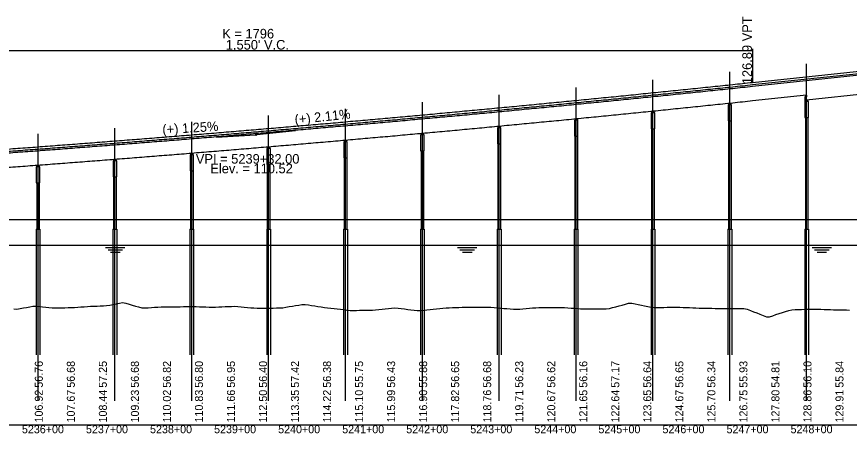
# Model space of a CAD drawing. Extents: x 2121671 to 2169879, y 557274 to 599957.
# Drawn here: x 2153126 to 2154426, y 579173 to 579824 of the extents above; entities that cross this region are included whole.
import ezdxf

# ---------------------------------------------------------------- set-up
doc = ezdxf.new("R2010")
doc.units = 0
for name, color, linetype in [('BR_CENTER LINES', 7, 'Continuous'), ('BR_CONCRETE', 7, 'Continuous'), ('BR_DETAILS', 7, 'Continuous'), ('BR_PRESTRESSED BEAM', 7, 'Continuous'), ('RD_DDB_GradeTX', 7, 'Continuous'), ('RD_DDB_Profile_Elev', 7, 'Continuous'), ('RD_DDB_Profile_EX', 7, 'Continuous'), ('RD_DDB_Profile_Lbl', 7, 'Continuous'), ('RD_DDB_Profile_PR', 7, 'Continuous'), ('RD_DDB_StaTX', 7, 'Continuous'), ('RD_DDB_StripGrade', 7, 'Continuous'), ('RD_DDB_VCLbl', 7, 'Continuous'), ('RD_GPK_Profile_Cell', 7, 'Continuous')]:
    doc.layers.add(name, color=color, linetype=linetype)

msp = doc.modelspace()

# ---------------------------------------------------------------- linework, layer by layer
at = {"layer": 'BR_CENTER LINES'}
for p, q in [((2154359.4, 579224.3), (2154359.4, 579750.2)), ((2154239.4, 579224.3), (2154239.4, 579737.6)), ((2154119.4, 579224.3), (2154119.4, 579725.2)), ((2153999.4, 579224.3), (2153999.4, 579713.3)), ((2153879.4, 579224.3), (2153879.4, 579701.7)), ((2153759.4, 579224.3), (2153759.4, 579690.5)), ((2153639.4, 579224.3), (2153639.4, 579679.8)), ((2153399.4, 579224.3), (2153399.4, 579659.5)), ((2153519.4, 579224.3), (2153519.4, 579669.4)), ((2153279.4, 579224.3), (2153279.4, 579649.9)), ((2153159.4, 579224.3), (2153159.4, 579640.8))]:
    msp.add_line(p, q, dxfattribs=at)
at = {"layer": 'BR_CONCRETE'}
for p, q in [((2154274.9, 579717.8), (2154567.9, 579748.7)), ((2154359.4, 579699), (2154356.7, 579699)), ((2154356.7, 579699), (2154356.7, 579666.7)), ((2154359.4, 579691.7), (2154359.4, 579699)), ((2154362.2, 579691.7), (2154359.4, 579691.7)), ((2154362.2, 579666.7), (2154362.2, 579691.7)), ((2154237.4, 579661.4), (2154237.4, 579492.4)), ((2154241.4, 579661.4), (2154241.4, 579492.4)), ((2154356.7, 579666.7), (2154362.2, 579666.7)), ((2154357.4, 579666.7), (2154357.4, 579492.4)), ((2154361.4, 579666.7), (2154361.4, 579492.4)), ((2154117.4, 579649), (2154117.4, 579492.4)), ((2154121.4, 579649), (2154121.4, 579492.4)), ((2153997.4, 579637.1), (2153997.4, 579492.4)), ((2154001.4, 579637.1), (2154001.4, 579492.4)), ((2153877.4, 579625.5), (2153877.4, 579492.4)), ((2153881.4, 579625.5), (2153881.4, 579492.4)), ((2153757.4, 579614.4), (2153757.4, 579492.4)), ((2153761.4, 579614.4), (2153761.4, 579492.4)), ((2153517.4, 579593.3), (2153517.4, 579492.4)), ((2153521.4, 579593.3), (2153521.4, 579492.4)), ((2153637.4, 579603.6), (2153637.4, 579492.4)), ((2153641.4, 579603.6), (2153641.4, 579492.4)), ((2153397.4, 579583.3), (2153397.4, 579492.4)), ((2153401.4, 579583.3), (2153401.4, 579492.4)), ((2153277.4, 579573.8), (2153277.4, 579492.4)), ((2153281.4, 579573.8), (2153281.4, 579492.4)), ((2153157.4, 579564.6), (2153157.4, 579492.4)), ((2153161.4, 579564.6), (2153161.4, 579492.4)), ((2153156.4, 579492.4), (2153156.4, 579296.1)), ((2153156.4, 579492.4), (2153162.4, 579492.4)), ((2153162.4, 579492.4), (2153162.4, 579296.1)), ((2153276.4, 579492.4), (2153276.4, 579296.1)), ((2153276.4, 579492.4), (2153282.4, 579492.4)), ((2153282.4, 579492.4), (2153282.4, 579296.1)), ((2153396.4, 579492.4), (2153396.4, 579296.1)), ((2153396.4, 579492.4), (2153402.4, 579492.4)), ((2153402.4, 579492.4), (2153402.4, 579296.1)), ((2153516.4, 579492.4), (2153516.4, 579296.1)), ((2153516.4, 579492.4), (2153522.4, 579492.4)), ((2153522.4, 579492.4), (2153522.4, 579296.1)), ((2153636.4, 579492.4), (2153636.4, 579296.1)), ((2153636.4, 579492.4), (2153642.4, 579492.4)), ((2153642.4, 579492.4), (2153642.4, 579296.1)), ((2153756.4, 579492.4), (2153756.4, 579296.1)), ((2153756.4, 579492.4), (2153762.4, 579492.4)), ((2153762.4, 579492.4), (2153762.4, 579296.1)), ((2153876.4, 579492.4), (2153876.4, 579296.1)), ((2153876.4, 579492.4), (2153882.4, 579492.4)), ((2153882.4, 579492.4), (2153882.4, 579296.1)), ((2153996.4, 579492.4), (2153996.4, 579296.1)), ((2153996.4, 579492.4), (2154002.4, 579492.4)), ((2154002.4, 579492.4), (2154002.4, 579296.1)), ((2154116.4, 579492.4), (2154116.4, 579296.1)), ((2154116.4, 579492.4), (2154122.4, 579492.4)), ((2154122.4, 579492.4), (2154122.4, 579296.1)), ((2154236.4, 579492.4), (2154236.4, 579296.1)), ((2154236.4, 579492.4), (2154242.4, 579492.4)), ((2154242.4, 579492.4), (2154242.4, 579296.1)), ((2154356.4, 579492.4), (2154356.4, 579296.1)), ((2154356.4, 579492.4), (2154362.4, 579492.4)), ((2154362.4, 579492.4), (2154362.4, 579296.1))]:
    msp.add_line(p, q, dxfattribs=at)
for points in [[(2154236.7, 579661.4), (2154242.2, 579661.4), (2154242.2, 579686.4), (2154236.7, 579686.4)], [(2154116.7, 579649), (2154122.2, 579649), (2154122.2, 579674), (2154116.7, 579674)], [(2153996.7, 579637.1), (2154002.2, 579637.1), (2154002.2, 579662.1), (2153996.7, 579662.1)], [(2153876.7, 579625.5), (2153882.2, 579625.5), (2153882.2, 579650.5), (2153876.7, 579650.5)], [(2153756.7, 579614.4), (2153762.2, 579614.4), (2153762.2, 579639.4), (2153756.7, 579639.4)], [(2153516.7, 579593.3), (2153522.2, 579593.3), (2153522.2, 579618.3), (2153516.7, 579618.3)], [(2153636.7, 579603.6), (2153642.2, 579603.6), (2153642.2, 579628.6), (2153636.7, 579628.6)], [(2153396.7, 579583.3), (2153402.2, 579583.3), (2153402.2, 579608.3), (2153396.7, 579608.3)], [(2153276.7, 579573.8), (2153282.2, 579573.8), (2153282.2, 579598.8), (2153276.7, 579598.8)], [(2153156.7, 579564.6), (2153162.2, 579564.6), (2153162.2, 579589.6), (2153156.7, 579589.6)]]:
    msp.add_lwpolyline(points, close=True, dxfattribs=at)
msp.add_spline([(2152724.9, 579587.5), (2152755.9, 579589.4), (2152786.9, 579591.4), (2152817.9, 579593.4), (2152848.9, 579595.4), (2152879.9, 579597.5), (2152910.9, 579599.6), (2152941.9, 579601.7), (2152972.9, 579603.8), (2153003.9, 579606), (2153034.9, 579608.2), (2153065.9, 579610.4), (2153096.9, 579612.6), (2153127.9, 579614.9), (2153158.9, 579617.2), (2153189.9, 579619.5), (2153220.9, 579621.9), (2153251.9, 579624.3), (2153282.9, 579626.7), (2153313.9, 579629.1), (2153344.9, 579631.6), (2153375.9, 579634), (2153406.9, 579636.6), (2153437.9, 579639.1), (2153468.9, 579641.7), (2153499.9, 579644.3), (2153530.9, 579646.9), (2153561.9, 579649.5), (2153592.9, 579652.2), (2153623.9, 579654.9), (2153654.9, 579657.6), (2153685.9, 579660.4), (2153716.9, 579663.1), (2153747.9, 579666), (2153778.9, 579668.8), (2153809.9, 579671.6), (2153840.9, 579674.5), (2153871.9, 579677.4), (2153902.9, 579680.4), (2153933.9, 579683.4), (2153964.9, 579686.3), (2153995.9, 579689.4), (2154026.9, 579692.4), (2154057.9, 579695.5), (2154088.9, 579698.6), (2154119.9, 579701.7), (2154150.9, 579704.9), (2154181.9, 579708.1), (2154212.9, 579711.3), (2154243.9, 579714.5), (2154274.9, 579717.8)], degree=3, dxfattribs=at)
at = {"layer": 'BR_DETAILS'}
for points in [[(2154357.9, 579701.5), (2154358.9, 579701.5), (2154358.9, 579699), (2154357.9, 579699)], [(2154237.9, 579688.9), (2154238.9, 579688.9), (2154238.9, 579686.4), (2154237.9, 579686.4)], [(2154239.9, 579688.9), (2154240.9, 579688.9), (2154240.9, 579686.4), (2154239.9, 579686.4)], [(2154359.9, 579694.2), (2154360.9, 579694.2), (2154360.9, 579691.7), (2154359.9, 579691.7)], [(2154117.9, 579676.5), (2154118.9, 579676.5), (2154118.9, 579674), (2154117.9, 579674)], [(2154119.9, 579676.5), (2154120.9, 579676.5), (2154120.9, 579674), (2154119.9, 579674)], [(2153997.9, 579664.6), (2153998.9, 579664.6), (2153998.9, 579662.1), (2153997.9, 579662.1)], [(2153999.9, 579664.6), (2154000.9, 579664.6), (2154000.9, 579662.1), (2153999.9, 579662.1)], [(2153877.9, 579653), (2153878.9, 579653), (2153878.9, 579650.5), (2153877.9, 579650.5)], [(2153879.9, 579653), (2153880.9, 579653), (2153880.9, 579650.5), (2153879.9, 579650.5)], [(2153637.9, 579631.1), (2153638.9, 579631.1), (2153638.9, 579628.6), (2153637.9, 579628.6)], [(2153639.9, 579631.1), (2153640.9, 579631.1), (2153640.9, 579628.6), (2153639.9, 579628.6)], [(2153757.9, 579641.9), (2153758.9, 579641.9), (2153758.9, 579639.4), (2153757.9, 579639.4)], [(2153759.9, 579641.9), (2153760.9, 579641.9), (2153760.9, 579639.4), (2153759.9, 579639.4)], [(2153517.9, 579620.8), (2153518.9, 579620.8), (2153518.9, 579618.3), (2153517.9, 579618.3)], [(2153519.9, 579620.8), (2153520.9, 579620.8), (2153520.9, 579618.3), (2153519.9, 579618.3)], [(2153397.9, 579610.8), (2153398.9, 579610.8), (2153398.9, 579608.3), (2153397.9, 579608.3)], [(2153399.9, 579610.8), (2153400.9, 579610.8), (2153400.9, 579608.3), (2153399.9, 579608.3)], [(2153157.9, 579592.1), (2153158.9, 579592.1), (2153158.9, 579589.6), (2153157.9, 579589.6)], [(2153159.9, 579592.1), (2153160.9, 579592.1), (2153160.9, 579589.6), (2153159.9, 579589.6)], [(2153277.9, 579601.3), (2153278.9, 579601.3), (2153278.9, 579598.8), (2153277.9, 579598.8)], [(2153279.9, 579601.3), (2153280.9, 579601.3), (2153280.9, 579598.8), (2153279.9, 579598.8)]]:
    msp.add_lwpolyline(points, close=True, dxfattribs=at)
at = {"layer": 'BR_PRESTRESSED BEAM'}
for p, q in [((2154274.9, 579715.3), (2154567.9, 579746.2)), ((2154359.4, 579694.2), (2154567.9, 579716.2)), ((2154274.9, 579692.8), (2154359.4, 579701.7))]:
    msp.add_line(p, q, dxfattribs=at)
for points in [[(2152724.9, 579585), (2152755.9, 579586.9), (2152786.9, 579588.9), (2152817.9, 579590.9), (2152848.9, 579592.9), (2152879.9, 579595), (2152910.9, 579597.1), (2152941.9, 579599.2), (2152972.9, 579601.3), (2153003.9, 579603.5), (2153034.9, 579605.7), (2153065.9, 579607.9), (2153096.9, 579610.1), (2153127.9, 579612.4), (2153158.9, 579614.7), (2153189.9, 579617), (2153220.9, 579619.4), (2153251.9, 579621.8), (2153282.9, 579624.2), (2153313.9, 579626.6), (2153344.9, 579629.1), (2153375.9, 579631.5), (2153406.9, 579634.1), (2153437.9, 579636.6), (2153468.9, 579639.2), (2153499.9, 579641.8), (2153530.9, 579644.4), (2153561.9, 579647), (2153592.9, 579649.7), (2153623.9, 579652.4), (2153654.9, 579655.1), (2153685.9, 579657.9), (2153716.9, 579660.6), (2153747.9, 579663.5), (2153778.9, 579666.3), (2153809.9, 579669.1), (2153840.9, 579672), (2153871.9, 579674.9), (2153902.9, 579677.9), (2153933.9, 579680.9), (2153964.9, 579683.8), (2153995.9, 579686.9), (2154026.9, 579689.9), (2154057.9, 579693), (2154088.9, 579696.1), (2154119.9, 579699.2), (2154150.9, 579702.4), (2154181.9, 579705.6), (2154212.9, 579708.8), (2154243.9, 579712), (2154274.9, 579715.3)], [(2152724.9, 579562.5), (2152755.9, 579564.4), (2152786.9, 579566.4), (2152817.9, 579568.4), (2152848.9, 579570.4), (2152879.9, 579572.5), (2152910.9, 579574.6), (2152941.9, 579576.7), (2152972.9, 579578.8), (2153003.9, 579581), (2153034.9, 579583.2), (2153065.9, 579585.4), (2153096.9, 579587.6), (2153127.9, 579589.9), (2153158.9, 579592.2), (2153189.9, 579594.5), (2153220.9, 579596.9), (2153251.9, 579599.3), (2153282.9, 579601.7), (2153313.9, 579604.1), (2153344.9, 579606.6), (2153375.9, 579609), (2153406.9, 579611.6), (2153437.9, 579614.1), (2153468.9, 579616.7), (2153499.9, 579619.3), (2153530.9, 579621.9), (2153561.9, 579624.5), (2153592.9, 579627.2), (2153623.9, 579629.9), (2153654.9, 579632.6), (2153685.9, 579635.4), (2153716.9, 579638.1), (2153747.9, 579641), (2153778.9, 579643.8), (2153809.9, 579646.6), (2153840.9, 579649.5), (2153871.9, 579652.4), (2153902.9, 579655.4), (2153933.9, 579658.4), (2153964.9, 579661.3), (2153995.9, 579664.4), (2154026.9, 579667.4), (2154057.9, 579670.5), (2154088.9, 579673.6), (2154119.9, 579676.7), (2154150.9, 579679.9), (2154181.9, 579683.1), (2154212.9, 579686.3), (2154243.9, 579689.5), (2154274.9, 579692.8)]]:
    msp.add_spline(points, degree=3, dxfattribs=at)
at = {"layer": 'RD_DDB_GradeTX'}
for p, q in [((2153561.6, 579645.9), (2153500.9, 579639.5)), ((2153438.1, 579635.6), (2153498.9, 579639.4))]:
    msp.add_line(p, q, dxfattribs=at)
msp.add_circle((2153499.9, 579639.4), 1, dxfattribs=at)
at = {"layer": 'RD_DDB_Profile_Elev'}
for p, q in [((2151922.4, 579507.4), (2155499.4, 579507.4)), ((2151953.5, 579467.4), (2156316.6, 579467.4)), ((2153265, 579463.7), (2153295, 579463.7)), ((2153814.5, 579463.7), (2153844.5, 579463.7)), ((2154368.1, 579463.7), (2154398.1, 579463.7)), ((2153268.8, 579459.9), (2153291.3, 579459.9)), ((2153272.5, 579456.2), (2153287.5, 579456.2)), ((2153818.2, 579459.9), (2153840.7, 579459.9)), ((2153822, 579456.2), (2153837, 579456.2)), ((2154371.8, 579459.9), (2154394.3, 579459.9)), ((2154375.6, 579456.2), (2154390.6, 579456.2))]:
    msp.add_line(p, q, dxfattribs=at)
at = {"layer": 'RD_DDB_Profile_EX'}
for points in [[(2153121.5, 579367.5), (2153126.5, 579367.4), (2153131.5, 579368.3), (2153136.5, 579369.2), (2153141.5, 579370.1), (2153146.5, 579371), (2153151.5, 579371.9), (2153156.5, 579371.9), (2153161.5, 579371.3), (2153166.5, 579370.8), (2153171.5, 579370.3), (2153176.5, 579369.7), (2153181.5, 579369.1), (2153186.5, 579369.2), (2153191.5, 579369.3), (2153196.5, 579369.4), (2153201.5, 579369.5), (2153206.5, 579369.6), (2153211.5, 579369.8), (2153216.5, 579370.1), (2153221.5, 579370.5)], [(2153221.5, 579370.5), (2153226.5, 579370.8), (2153231.5, 579371.1), (2153236.5, 579371.5), (2153241.5, 579371.7), (2153246.5, 579371.9), (2153251.5, 579372.1), (2153256.5, 579372.2), (2153261.5, 579372.4), (2153266.5, 579372.8), (2153271.5, 579373.7), (2153276.5, 579374.7), (2153281.5, 579375.6), (2153286.5, 579376.5), (2153291.5, 579377.5), (2153296.5, 579376.6), (2153301.5, 579375.1), (2153306.5, 579373.6), (2153311.5, 579372.1), (2153316.5, 579370.7), (2153321.5, 579369.2), (2153326.5, 579369.2), (2153331.5, 579369.5), (2153336.5, 579369.9), (2153341.5, 579370.2), (2153346.5, 579370.5), (2153351.5, 579370.8), (2153356.5, 579371.1), (2153361.5, 579370.9), (2153366.5, 579370.9), (2153371.5, 579371), (2153376.5, 579371), (2153381.5, 579371.1), (2153386.5, 579371.2), (2153391.5, 579371.2), (2153396.5, 579371.5), (2153401.5, 579371.3), (2153406.5, 579371.2), (2153411.5, 579371), (2153416.5, 579370.9), (2153421.5, 579370.7), (2153426.5, 579370.6), (2153431.5, 579370.4), (2153436.5, 579370.6), (2153441.5, 579370.8), (2153446.5, 579371), (2153451.5, 579371.2), (2153456.5, 579371.4), (2153461.5, 579371.6), (2153466.5, 579371.7), (2153471.5, 579371.3), (2153476.5, 579370.9), (2153481.5, 579370.4), (2153486.5, 579370), (2153491.5, 579369.5), (2153496.5, 579369.1), (2153501.5, 579368.6), (2153506.5, 579368.6), (2153511.5, 579368.7), (2153516.5, 579368.8), (2153521.5, 579368.9), (2153526.5, 579369), (2153531.5, 579369.1), (2153536.5, 579369.1), (2153541.5, 579369.5), (2153546.5, 579370.4), (2153551.5, 579371.2), (2153556.5, 579372), (2153561.5, 579372.9), (2153566.5, 579373.7), (2153571.5, 579374.5), (2153576.5, 579374.7), (2153581.5, 579374), (2153586.5, 579373.2), (2153591.5, 579372.4), (2153596.5, 579371.6), (2153601.5, 579370.9), (2153606.5, 579370.1), (2153611.5, 579369.5), (2153616.5, 579368.9), (2153621.5, 579368.3), (2153626.5, 579367.7), (2153631.5, 579367.1), (2153636.5, 579366.5), (2153641.5, 579365.9), (2153646.5, 579365.3), (2153651.5, 579365.4), (2153656.5, 579365.4), (2153661.5, 579365.5), (2153666.5, 579365.6), (2153671.5, 579365.6), (2153676.5, 579365.7), (2153681.5, 579365.8), (2153686.5, 579366.1), (2153691.5, 579366.6), (2153696.5, 579367.1), (2153701.5, 579367.6), (2153706.5, 579368.1), (2153711.5, 579368.6), (2153716.5, 579369.1), (2153721.5, 579368.8)], [(2153721.5, 579368.8), (2153726.5, 579368.1), (2153731.5, 579367.5), (2153736.5, 579366.9), (2153741.5, 579366.2), (2153746.5, 579365.6), (2153751.5, 579365), (2153756.5, 579365), (2153761.5, 579365.6), (2153766.5, 579366.1), (2153771.5, 579366.6), (2153776.5, 579367.2), (2153781.5, 579367.7), (2153786.5, 579368.2), (2153791.5, 579368.8), (2153796.5, 579369.3), (2153801.5, 579369.5), (2153806.5, 579369.7), (2153811.5, 579369.8), (2153816.5, 579370), (2153821.5, 579370.2), (2153826.5, 579370.4), (2153831.5, 579370.6), (2153836.5, 579370.6), (2153841.5, 579370.6), (2153846.5, 579370.5), (2153851.5, 579370.5), (2153856.5, 579370.4), (2153861.5, 579370.4), (2153866.5, 579370.3), (2153871.5, 579370), (2153876.5, 579369.5), (2153881.5, 579369), (2153886.5, 579368.5), (2153891.5, 579368.1), (2153896.5, 579367.6), (2153901.5, 579367.1), (2153906.5, 579367), (2153911.5, 579367.4), (2153916.5, 579367.8), (2153921.5, 579368.3), (2153926.5, 579368.7), (2153931.5, 579369.1), (2153936.5, 579369.5), (2153941.5, 579369.9), (2153946.5, 579369.9), (2153951.5, 579369.9), (2153956.5, 579369.9), (2153961.5, 579369.9), (2153966.5, 579369.9), (2153971.5, 579369.9), (2153976.5, 579369.9), (2153981.5, 579369.6), (2153986.5, 579369.2), (2153991.5, 579368.9), (2153996.5, 579368.6), (2154001.5, 579368.3), (2154006.5, 579367.9), (2154011.5, 579367.6), (2154016.5, 579367.6), (2154021.5, 579367.6), (2154026.5, 579367.6), (2154031.5, 579367.6), (2154036.5, 579367.6), (2154041.5, 579367.6), (2154046.5, 579367.5), (2154051.5, 579368.2), (2154056.5, 579369.6), (2154061.5, 579370.9), (2154066.5, 579372.3), (2154071.5, 579373.7), (2154076.5, 579375.1), (2154081.5, 579376.4), (2154086.5, 579376.6), (2154091.5, 579375.5), (2154096.5, 579374.5), (2154101.5, 579373.4), (2154106.5, 579372.3), (2154111.5, 579371.3), (2154116.5, 579370.2), (2154121.5, 579369.6), (2154126.5, 579369.7), (2154131.5, 579369.9), (2154136.5, 579370), (2154141.5, 579370.2), (2154146.5, 579370.3), (2154151.5, 579370.5), (2154156.5, 579370.6), (2154161.5, 579370.4), (2154166.5, 579370.1), (2154171.5, 579369.9), (2154176.5, 579369.6), (2154181.5, 579369.4), (2154186.5, 579369.1), (2154191.5, 579368.9), (2154196.5, 579368.8), (2154201.5, 579368.7), (2154206.5, 579368.7), (2154211.5, 579368.6), (2154216.5, 579368.5), (2154221.5, 579368.5)], [(2154221.5, 579368.5), (2154226.5, 579368.4), (2154231.5, 579368.4), (2154236.5, 579368.4), (2154241.5, 579368.3), (2154246.5, 579368.3), (2154251.5, 579368.2), (2154256.5, 579368.2), (2154261.5, 579368.2), (2154266.5, 579367), (2154271.5, 579365.1), (2154276.5, 579363.2), (2154281.5, 579361.3), (2154286.5, 579359.3), (2154291.5, 579357.4), (2154296.5, 579355.5), (2154301.5, 579355.3), (2154306.5, 579357), (2154311.5, 579358.7), (2154316.5, 579360.4), (2154321.5, 579362.1), (2154326.5, 579363.7), (2154331.5, 579365.4), (2154336.5, 579366.4), (2154341.5, 579366.6), (2154346.5, 579366.7), (2154351.5, 579366.9), (2154356.5, 579367), (2154361.5, 579367.2), (2154366.5, 579367.3), (2154371.5, 579367.3), (2154376.5, 579367.2), (2154381.5, 579367), (2154386.5, 579366.8), (2154391.5, 579366.7), (2154396.5, 579366.5), (2154401.5, 579366.3), (2154406.5, 579366.2), (2154411.5, 579366.1), (2154416.5, 579366), (2154421.5, 579366), (2154426.5, 579365.9)]]:
    msp.add_lwpolyline(points, dxfattribs=at)
at = {"layer": 'RD_DDB_Profile_PR'}
msp.add_line((2154274.9, 579721.3), (2154567.9, 579752.2), dxfattribs=at)
msp.add_spline([(2152724.9, 579591), (2152755.9, 579593), (2152786.9, 579594.9), (2152817.9, 579596.9), (2152848.9, 579599), (2152879.9, 579601), (2152910.9, 579603.1), (2152941.9, 579605.2), (2152972.9, 579607.4), (2153003.9, 579609.5), (2153034.9, 579611.7), (2153065.9, 579613.9), (2153096.9, 579616.2), (2153127.9, 579618.4), (2153158.9, 579620.7), (2153189.9, 579623.1), (2153220.9, 579625.4), (2153251.9, 579627.8), (2153282.9, 579630.2), (2153313.9, 579632.6), (2153344.9, 579635.1), (2153375.9, 579637.6), (2153406.9, 579640.1), (2153437.9, 579642.6), (2153468.9, 579645.2), (2153499.9, 579647.8), (2153530.9, 579650.4), (2153561.9, 579653.1), (2153592.9, 579655.7), (2153623.9, 579658.4), (2153654.9, 579661.2), (2153685.9, 579663.9), (2153716.9, 579666.7), (2153747.9, 579669.5), (2153778.9, 579672.3), (2153809.9, 579675.2), (2153840.9, 579678.1), (2153871.9, 579681), (2153902.9, 579683.9), (2153933.9, 579686.9), (2153964.9, 579689.9), (2153995.9, 579692.9), (2154026.9, 579696), (2154057.9, 579699), (2154088.9, 579702.1), (2154119.9, 579705.3), (2154150.9, 579708.4), (2154181.9, 579711.6), (2154212.9, 579714.8), (2154243.9, 579718), (2154274.9, 579721.3)], degree=3, dxfattribs=at)
at = {"layer": 'RD_DDB_VCLbl'}
for p, q in [((2152724.9, 579771.3), (2154274.9, 579771.3)), ((2154274.9, 579773.8), (2154274.9, 579721.3))]:
    msp.add_line(p, q, dxfattribs=at)
at = {"layer": 'RD_GPK_Profile_Cell'}
msp.add_line((2151067.9, 579186.8), (2157367.9, 579186.8), dxfattribs=at)

# ---------------------------------------------------------------- texts
at = {"layer": 'RD_DDB_GradeTX'}
for s, rotation, p in [('(+) 2.11%', 6.0299, (2153560.8, 579655.8)), ('(+) 1.25%', 3.5756, (2153354, 579640.2))]:
    msp.add_text(s, height=15, rotation=rotation, dxfattribs=at).set_placement(p)
at = {"layer": 'RD_DDB_Profile_Lbl'}
for s, p in [('VPI = 5239+32.00', (2153405.8, 579594.4)), ('Elev. = 110.52', (2153428.4, 579579.4))]:
    msp.add_text(s, height=15, dxfattribs=at).set_placement(p)
at = {"layer": 'RD_DDB_StaTX'}
for s, p in [('5236+00', (2153134.3, 579173.5)), ('5237+00', (2153234.3, 579173.5)), ('5238+00', (2153334.3, 579173.5)), ('5239+00', (2153434.3, 579173.5)), ('5240+00', (2153534.3, 579173.5)), ('5241+00', (2153634.3, 579173.5)), ('5242+00', (2153734.3, 579173.5)), ('5243+00', (2153834.3, 579173.5)), ('5244+00', (2153934.3, 579173.5)), ('5245+00', (2154034.3, 579173.5)), ('5246+00', (2154134.3, 579173.5)), ('5247+00', (2154234.3, 579173.5)), ('5248+00', (2154334.3, 579173.5))]:
    msp.add_text(s, height=12.5, dxfattribs=at).set_placement(p)
at = {"layer": 'RD_DDB_StripGrade'}
for s, height, p in [('126.89 VPT', 15, (2154273.9, 579718.5)), ('56.76', 12.5, (2153166.9, 579244.6)), ('56.68', 12.5, (2153216.9, 579244.6)), ('57.25', 12.5, (2153266.9, 579244.6)), ('56.68', 12.5, (2153316.9, 579244.6)), ('56.82', 12.5, (2153366.9, 579244.6)), ('56.80', 12.5, (2153416.9, 579244.6)), ('56.95', 12.5, (2153466.9, 579244.6)), ('56.40', 12.5, (2153516.9, 579244.6)), ('57.42', 12.5, (2153566.9, 579244.6)), ('56.38', 12.5, (2153616.9, 579244.6)), ('55.75', 12.5, (2153666.9, 579244.6)), ('56.43', 12.5, (2153716.9, 579244.6)), ('55.88', 12.5, (2153766.9, 579244.6)), ('56.65', 12.5, (2153816.9, 579244.6)), ('56.68', 12.5, (2153866.9, 579244.6)), ('56.23', 12.5, (2153916.9, 579244.6)), ('56.62', 12.5, (2153966.9, 579244.6)), ('56.16', 12.5, (2154016.9, 579244.6)), ('57.17', 12.5, (2154066.9, 579244.6)), ('56.64', 12.5, (2154116.9, 579244.6)), ('56.65', 12.5, (2154166.9, 579244.6)), ('56.34', 12.5, (2154216.9, 579244.6)), ('55.93', 12.5, (2154266.9, 579244.6)), ('54.81', 12.5, (2154316.9, 579244.6)), ('56.10', 12.5, (2154366.9, 579244.6)), ('55.84', 12.5, (2154416.9, 579244.6)), ('106.92', 12.5, (2153166.9, 579190.3)), ('107.67', 12.5, (2153216.9, 579190.3)), ('108.44', 12.5, (2153266.9, 579190.3)), ('109.23', 12.5, (2153316.9, 579190.3)), ('110.02', 12.5, (2153366.9, 579190.3)), ('110.83', 12.5, (2153416.9, 579190.3)), ('111.66', 12.5, (2153466.9, 579190.3)), ('112.50', 12.5, (2153516.9, 579190.3)), ('113.35', 12.5, (2153566.9, 579190.3)), ('114.22', 12.5, (2153616.9, 579190.3)), ('115.10', 12.5, (2153666.9, 579190.3)), ('115.99', 12.5, (2153716.9, 579190.3)), ('116.90', 12.5, (2153766.9, 579190.3)), ('117.82', 12.5, (2153816.9, 579190.3)), ('118.76', 12.5, (2153866.9, 579190.3)), ('119.71', 12.5, (2153916.9, 579190.3)), ('120.67', 12.5, (2153966.9, 579190.3)), ('121.65', 12.5, (2154016.9, 579190.3)), ('122.64', 12.5, (2154066.9, 579190.3)), ('123.65', 12.5, (2154116.9, 579190.3)), ('124.67', 12.5, (2154166.9, 579190.3)), ('125.70', 12.5, (2154216.9, 579190.3)), ('126.75', 12.5, (2154266.9, 579190.3)), ('127.80', 12.5, (2154316.9, 579190.3)), ('128.86', 12.5, (2154366.9, 579190.3)), ('129.91', 12.5, (2154416.9, 579190.3))]:
    msp.add_text(s, height=height, rotation=90, dxfattribs=at).set_placement(p)
at = {"layer": 'RD_DDB_VCLbl'}
for s, p in [('K = 1796', (2153447.1, 579789.9)), ("1,550' V.C.", (2153452.6, 579772.5))]:
    msp.add_text(s, height=15, dxfattribs=at).set_placement(p)

doc.saveas('drawing.dxf')
